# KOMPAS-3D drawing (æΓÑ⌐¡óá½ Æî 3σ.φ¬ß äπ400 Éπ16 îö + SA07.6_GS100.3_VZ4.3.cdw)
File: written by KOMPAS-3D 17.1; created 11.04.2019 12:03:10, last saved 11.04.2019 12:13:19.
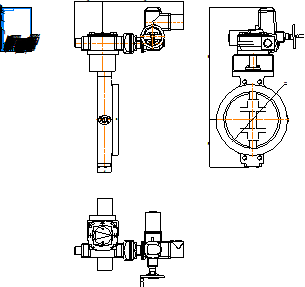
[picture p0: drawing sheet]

Sheet 1: A4, portrait

Title block, sheet 1: name: Стейнвал ТМ 3х.экс / Ду400 Ру16 МФ + SA07.6_GS100.3_VZ4.3; material: Внимание! Данный продукт является объектом авторского права ООО «Торговый Дом АДЛ». / Запрещается изменение, копирование, распространение / (в том числе путем копирования на другие сайты и ресурсы в Интернете) / или любое иное использование информации и объектов без предварительного / согласия правообладателя (ООО «Торговый Дом АДЛ»).; mass: 255,93; sheets: 1; organisation: ООО "Торговый дом АДЛ"; sheet format: A4; stored path: \\adlc.lan\data\АДЛ_ПКД\3D-модели\ADL production\Дисковые поворотные затворы СТЕЙНВАЛ\Трехэксцентриковый\Стейнвал м-ф\С эл.приводом\KOMPAS 2D\Стейнвал ТМ 3х.экс  Ду400 Ру16 МФ + SA07.6_GS100.3_VZ4.3.cdw

Views: Вид 1, Проекционный вид 2, Проекционный вид 3
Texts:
  user
Dimensions and other numbers on the sheet: 485; 98; 189; 549; 758,7; 325; 387; 1:1; 1; 255,93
